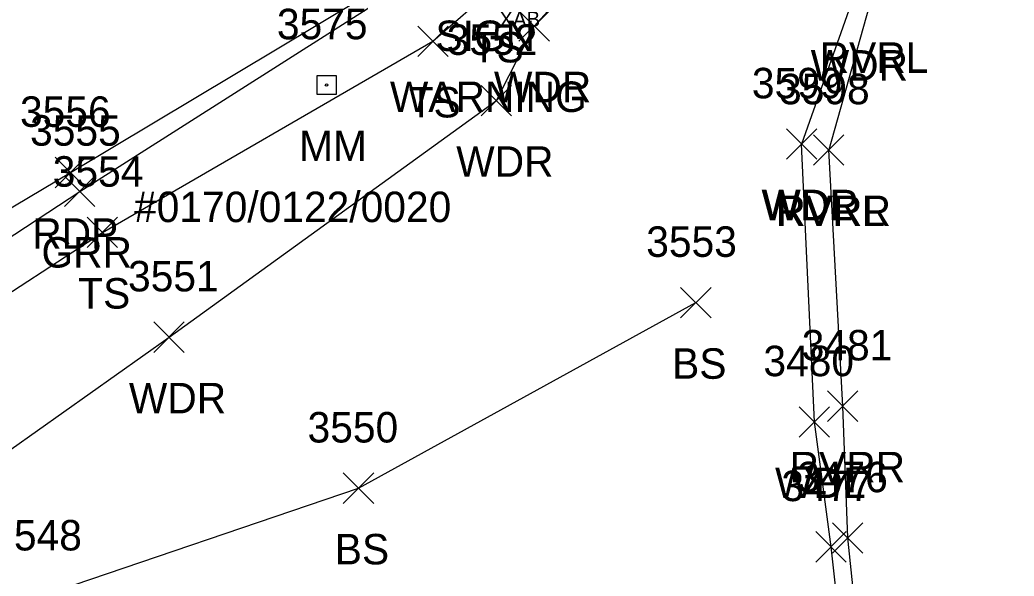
# Model space of a CAD drawing. Extents: x 1443590 to 1445966, y 578314 to 580556.
# Drawn here: x 1444183.6 to 1444248.9, y 578887.6 to 578924.1 of the extents above; entities that cross this region are included whole.
import ezdxf

# ---------------------------------------------------------------- set-up
doc = ezdxf.new("R2010")
doc.units = 0
for name, color, linetype in [('B_A', 7, 'Continuous'), ('L_A', 7, 'Continuous'), ('L_I', 7, 'Continuous'), ('L_TIC', 7, 'Continuous'), ('LAWA', 7, 'Continuous'), ('LAWE', 7, 'Continuous'), ('LELB', 7, 'Continuous'), ('P_A', 7, 'Continuous'), ('P_I', 7, 'Continuous'), ('P_TIC', 7, 'Continuous'), ('PET', 7, 'Continuous'), ('R_A', 7, 'Continuous'), ('R_I', 7, 'Continuous'), ('R_TIC', 7, 'Continuous'), ('RGR', 7, 'Continuous'), ('S_A', 7, 'Continuous'), ('S_C', 7, 'Continuous'), ('S_I', 7, 'Continuous'), ('SRM', 7, 'Continuous')]:
    doc.layers.add(name, color=color, linetype=linetype)

msp = doc.modelspace()

# ---------------------------------------------------------------- linework, layer by layer
at = {"layer": 'L_TIC'}
for points in [[(1444216.379, 578922.703), (1444218.379, 578924.703)], [(1444218.379, 578922.703), (1444216.379, 578924.703)], [(1444209.734, 578921.706), (1444211.734, 578923.706)], [(1444211.734, 578921.706), (1444209.734, 578923.706)], [(1444213.902, 578917.812), (1444215.902, 578919.812)], [(1444215.902, 578917.812), (1444213.902, 578919.812)], [(1444233.94, 578914.96), (1444235.94, 578916.96)], [(1444235.94, 578914.96), (1444233.94, 578916.96)], [(1444233.94, 578914.96), (1444235.94, 578916.96)], [(1444235.94, 578914.96), (1444233.94, 578916.96)], [(1444235.716, 578914.571), (1444237.716, 578916.571)], [(1444237.716, 578914.571), (1444235.716, 578916.571)], [(1444235.716, 578914.571), (1444237.716, 578916.571)], [(1444237.716, 578914.571), (1444235.716, 578916.571)], [(1444188.038, 578909.162), (1444190.038, 578911.162)], [(1444190.038, 578909.162), (1444188.038, 578911.162)], [(1444226.997, 578904.556), (1444228.997, 578906.556)], [(1444228.997, 578904.556), (1444226.997, 578906.556)], [(1444192.413, 578902.289), (1444194.413, 578904.289)], [(1444194.413, 578902.289), (1444192.413, 578904.289)], [(1444236.637, 578897.76), (1444238.637, 578899.76)], [(1444238.637, 578897.76), (1444236.637, 578899.76)], [(1444234.775, 578896.725), (1444236.775, 578898.725)], [(1444236.775, 578896.725), (1444234.775, 578898.725)], [(1444204.853, 578892.373), (1444206.853, 578894.373)], [(1444206.853, 578892.373), (1444204.853, 578894.373)], [(1444236.961, 578889.11), (1444238.961, 578891.11)], [(1444238.961, 578889.11), (1444236.961, 578891.11)], [(1444235.869, 578888.526), (1444237.869, 578890.526)], [(1444237.869, 578888.526), (1444235.869, 578890.526)]]:
    msp.add_lwpolyline(points, dxfattribs=at)
at = {"layer": 'LAWA'}
for points in [[(1444048.103, 578821.317), (1444063.675, 578832.306), (1444080.367, 578840.962), (1444085.338, 578844.038), (1444109.175, 578848.22), (1444135.339, 578861.472), (1444163.107, 578880.72), (1444179.566, 578893.485), (1444193.413, 578903.289), (1444214.902, 578918.812), (1444217.379, 578923.703), (1444222.652, 578929.511), (1444230.186, 578931.189), (1444234.323, 578936.96), (1444238.172, 578925.123), (1444234.94, 578915.96)], [(1444260.268, 578793.868), (1444256.273, 578810.07), (1444249.028, 578829.591), (1444245.361, 578844.407), (1444241.92, 578858.183), (1444238.607, 578873.983), (1444236.869, 578889.526), (1444235.775, 578897.725), (1444234.94, 578915.96)]]:
    msp.add_lwpolyline(points, dxfattribs=at)
at = {"layer": 'LAWE'}
for points in [[(1444132.863, 579092.153), (1444138.962, 579083.211), (1444141.194, 579057.076), (1444148.069, 579045.276), (1444167.245, 579025.017), (1444174.77, 579019.565), (1444188.422, 579002.667), (1444202.859, 578984.811), (1444211.076, 578975.971), (1444218.072, 578968.054), (1444223.321, 578965.926), (1444225.772, 578959.776), (1444234.825, 578940.518), (1444239.555, 578925.633), (1444236.716, 578915.571)], [(1444257.892, 578810.311), (1444250.172, 578829.867), (1444247.267, 578845.179), (1444243.67, 578859.095), (1444239.614, 578874.345), (1444237.961, 578890.11), (1444237.637, 578898.76), (1444236.716, 578915.571)]]:
    msp.add_lwpolyline(points, dxfattribs=at)
at = {"layer": 'LELB'}
for points in [[(1443615.531, 578549.091), (1443647.151, 578571.871), (1443656.709, 578577.237), (1443699.776, 578605.862), (1443739.161, 578631.364), (1443774.006, 578653.63), (1443806.329, 578675.435), (1443846.662, 578699.7), (1443880.838, 578720.785), (1443915.446, 578744.078), (1443953.643, 578767.009), (1443986.396, 578787.388), (1444018.894, 578809.069), (1444030.213, 578814.653), (1444042.784, 578823.315), (1444045.841, 578825.913), (1444071.112, 578843.042), (1444083.631, 578848.629), (1444101.331, 578858.927), (1444132.811, 578873.635), (1444159.481, 578890.915), (1444189.038, 578910.162), (1444210.734, 578922.706), (1444214.873, 578926.317)], [(1444185.002, 578886.289), (1444205.853, 578893.373), (1444227.997, 578905.556)]]:
    msp.add_lwpolyline(points, dxfattribs=at)
at = {"layer": 'P_TIC'}
for points in [[(1444185.944, 578913.089), (1444187.944, 578915.089)], [(1444187.944, 578913.089), (1444185.944, 578915.089)]]:
    msp.add_lwpolyline(points, dxfattribs=at)
at = {"layer": 'PET'}
msp.add_lwpolyline([(1443612.395, 578554.371), (1443645.037, 578575.451), (1443657.241, 578583.198), (1443697.445, 578609.181), (1443737.284, 578634.547), (1443772.294, 578657.287), (1443804.753, 578678.072), (1443844.063, 578703.73), (1443878.038, 578725.084), (1443913.763, 578747.61), (1443950.95, 578770.858), (1443984.55, 578791.673), (1444017.367, 578812.185), (1444029.713, 578820.039), (1444042.885, 578828.092), (1444081.781, 578851.73), (1444099.653, 578862.289), (1444128.943, 578879.476), (1444156.819, 578896.169), (1444186.944, 578914.089), (1444214.074, 578930.352)], dxfattribs=at)
at = {"layer": 'R_TIC'}
for points in [[(1444186.55, 578911.853), (1444188.55, 578913.853)], [(1444188.55, 578911.853), (1444186.55, 578913.853)]]:
    msp.add_lwpolyline(points, dxfattribs=at)
at = {"layer": 'RGR'}
msp.add_lwpolyline([(1444132.811, 578873.635), (1444157.74, 578893.28), (1444187.55, 578912.853), (1444214.238, 578929.821)], dxfattribs=at)
at = {"layer": 'SRM'}
msp.add_lwpolyline([(1444203.129, 578920.462), (1444204.379, 578920.462), (1444204.379, 578919.212), (1444203.129, 578919.212)], close=True, dxfattribs=at)
msp.add_circle((1444203.754, 578919.837), 0.0833, dxfattribs=at)

# ---------------------------------------------------------------- texts
at = {"layer": 'B_A'}
msp.add_text('XAB', height=1, dxfattribs=at).set_placement((1444215.097, 578923.661))
at = {"layer": 'L_A'}
for s, p in [('TS', (1444213.283, 578921.317)), ('WDR', (1444235.534, 578920.123)), ('RVRL', (1444236.122, 578920.633)), ('WDR', (1444214.742, 578918.703)), ('TS', (1444209.143, 578917.706)), ('WDR', (1444212.264, 578913.812)), ('WDR', (1444232.302, 578910.96)), ('WDL', (1444232.357, 578910.96)), ('RVRR', (1444233.228, 578910.571)), ('RVRL', (1444233.283, 578910.571)), ('TS', (1444187.448, 578905.162)), ('BS', (1444226.438, 578900.556)), ('WDR', (1444190.776, 578898.289)), ('RVRR', (1444234.148, 578893.76)), ('WDL', (1444233.192, 578892.725)), ('BS', (1444204.294, 578888.373))]:
    msp.add_text(s, height=2, dxfattribs=at).set_placement(p)
at = {"layer": 'L_I'}
for s, p in [('3552', (1444211.642, 578921.812)), ('3599', (1444231.672, 578918.96)), ('3599', (1444231.672, 578918.96)), ('3598', (1444233.456, 578918.571)), ('3598', (1444233.456, 578918.571)), ('3554', (1444185.778, 578913.162)), ('3553', (1444224.738, 578908.556)), ('3551', (1444190.721, 578906.289)), ('3481', (1444234.944, 578901.76)), ('3480', (1444232.429, 578900.725)), ('3550', (1444202.506, 578896.373)), ('3476', (1444234.646, 578893.11)), ('3477', (1444233.61, 578892.526)), ('3548', (1444181.742, 578889.289))]:
    msp.add_text(s, height=2, dxfattribs=at).set_placement(p)
at = {"layer": 'P_A'}
msp.add_text('RDP', height=2, dxfattribs=at).set_placement((1444184.433, 578909.089))
at = {"layer": 'P_I'}
msp.add_text('3556', height=2, dxfattribs=at).set_placement((1444183.63, 578917.089))
at = {"layer": 'R_A'}
msp.add_text('GRR', height=2, dxfattribs=at).set_placement((1444185.038, 578907.853))
at = {"layer": 'R_I'}
msp.add_text('3555', height=2, dxfattribs=at).set_placement((1444184.29, 578915.853))
at = {"layer": 'S_A'}
for s, p in [('SIGN', (1444210.902, 578922.063)), ('MM', (1444201.943, 578914.837))]:
    msp.add_text(s, height=2, dxfattribs=at).set_placement(p)
at = {"layer": 'S_C'}
for s, p in [('WARNING', (1444207.91, 578918.063)), ('#0170/0122/0020', (1444191.116, 578910.837))]:
    msp.add_text(s, height=2, dxfattribs=at).set_placement(p)
at = {"layer": 'S_I'}
msp.add_text('3575', height=2, dxfattribs=at).set_placement((1444200.494, 578922.837))

doc.saveas('drawing.dxf')
